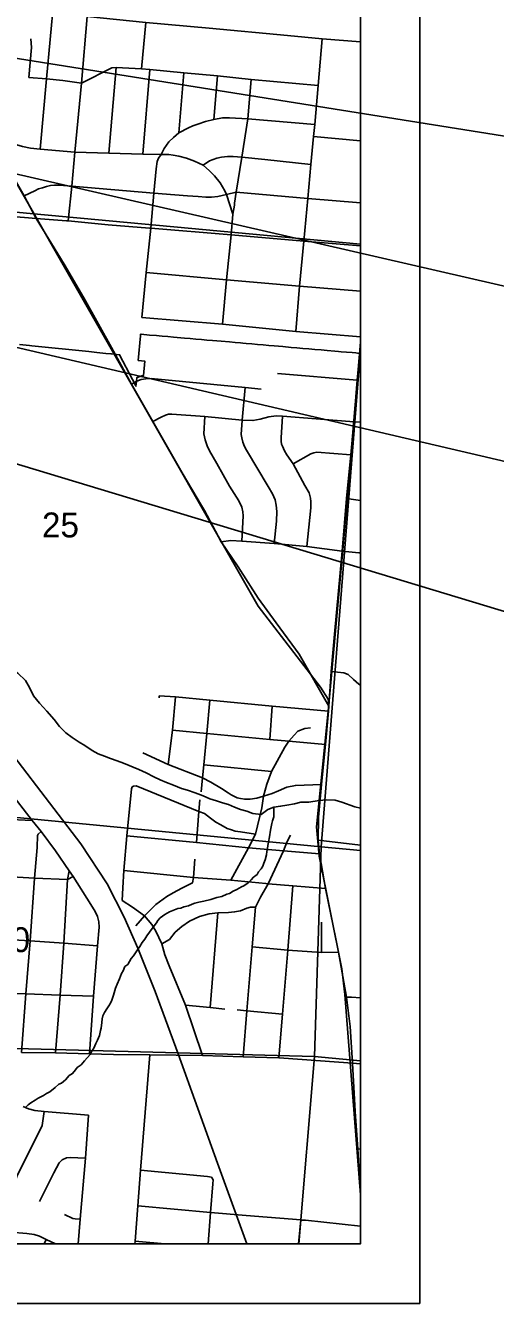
# Model space of a CAD drawing. Extents: x 0 to 34, y 0 to 22.
# Drawn here: x 8.337 to 9.127, y 14 to 16.149 of the extents above; entities that cross this region are included whole.
import ezdxf

# ---------------------------------------------------------------- set-up
doc = ezdxf.new("R2010")
doc.units = 0
for name, color, linetype in [('Default', 7, 'Continuous'), ('GM_X_City_Street', 7, 'Continuous'), ('GM_X_County_Road', 7, 'Continuous'), ('GM_X_Minor_River', 7, 'Continuous'), ('GM_X_Rail_Line', 7, 'Continuous'), ('GM_X_Section', 7, 'Continuous'), ('GM_X_Section_Text', 7, 'Continuous'), ('GM_X_State_Route', 7, 'Continuous'), ('GM_X_Township_Road', 7, 'Continuous'), ('SH_Data', 7, 'Continuous'), ('SH_Text', 7, 'Continuous')]:
    doc.layers.add(name, color=color, linetype=linetype)

msp = doc.modelspace()

# ---------------------------------------------------------------- linework, layer by layer
at = {"layer": 'Default'}
for points in [[(8.9, 15.7814), (8.9, 16.8048), (8.0016, 16.8868), (7.9035, 15.8736)], [(8.9, 15.6028), (8.9, 15.7814), (7.9035, 15.8736), (7.8278, 14.865), (8.8341, 14.7681)], [(8.9, 14.7619), (8.9, 15.6028), (8.8341, 14.7681)], [(8.9, 14.4077), (8.9, 14.7619), (8.8341, 14.7681), (8.8225, 14.415)], [(7.7734, 14.1), (8.7964, 14.1), (8.8225, 14.415), (7.7982, 14.4425)], [(8.7964, 14.1), (8.9, 14.1), (8.9, 14.4077), (8.8225, 14.415)]]:
    msp.add_lwpolyline(points, close=True, dxfattribs=at)
at = {"layer": 'GM_X_City_Street'}
for p, q in [((8.5321, 16.0763), (8.5389, 16.154)), ((8.4767, 15.9342), (8.4895, 16.0786)), ((8.5343, 15.9328), (8.5458, 16.0748)), ((8.6536, 15.991), (8.6598, 16.0643)), ((8.8213, 15.9624), (8.9, 15.9549)), ((8.3549, 15.8247), (8.4056, 15.8205)), ((8.7605, 15.5638), (8.8946, 15.5526)), ((8.8768, 15.3536), (8.9, 15.3501)), ((8.7474, 14.9484), (8.7515, 15.0045)), ((8.6369, 14.9057), (8.7502, 14.8945)), ((8.8291, 14.7791), (8.9, 14.7707)), ((8.6194, 14.7164), (8.6214, 14.7469)), ((8.6475, 14.4979), (8.6604, 14.6567)), ((8.8347, 14.59), (8.8343, 14.6409)), ((8.771, 14.4125), (8.8867, 14.4043)), ((8.8867, 14.4043), (8.9, 14.4032)), ((8.8954, 14.26), (8.9, 14.2595)), ((8.7961, 14.1), (8.7997, 14.1404)), ((8.3683, 14.1), (8.3717, 14.1074)), ((8.5713, 14.1), (8.521, 14.1049))]:
    msp.add_line(p, q, dxfattribs=at)
for points in [[(8.4086, 15.8203), (8.4148, 15.879), (8.42, 15.9362), (8.4311, 16.0521), (8.4407, 16.1639), (8.4425, 16.1849), (8.4481, 16.2479), (8.4567, 16.3286), (8.4603, 16.3382), (8.4723, 16.4504), (8.4774, 16.5183), (8.4829, 16.5851), (8.4866, 16.6299), (8.4884, 16.6515), (8.4965, 16.7464), (8.5006, 16.7499)], [(8.3616, 15.9413), (8.372, 16.0594), (8.3846, 16.1916)], [(8.4407, 16.1639), (8.5389, 16.154), (8.6455, 16.1443), (8.7774, 16.1321), (8.8358, 16.1268), (8.9, 16.1214)], [(8.3425, 16.0616), (8.3469, 16.1121), (8.3456, 16.1268)], [(8.7915, 15.6345), (8.7974, 15.7108), (8.8048, 15.7862), (8.8116, 15.8583), (8.8167, 15.9154), (8.8213, 15.9624), (8.8234, 15.9828), (8.8288, 16.0481), (8.8358, 16.1268)], [(8.3425, 16.0616), (8.372, 16.0594), (8.3996, 16.0567), (8.4311, 16.0521), (8.4822, 16.0777), (8.4895, 16.0786), (8.5321, 16.0763), (8.5458, 16.0748), (8.603, 16.0697), (8.6598, 16.0643), (8.7162, 16.0585), (8.8288, 16.0481)], [(8.5322, 15.6579), (8.5397, 15.7337), (8.5476, 15.8082), (8.5528, 15.8669), (8.5563, 15.9081), (8.5581, 15.9205), (8.5603, 15.9258), (8.5652, 15.9321), (8.57, 15.9422), (8.5777, 15.9533), (8.5857, 15.9609), (8.5945, 15.9686), (8.603, 16.0697)], [(8.688, 15.8471), (8.6884, 15.8502), (8.6913, 15.8688), (8.7005, 15.9274), (8.7106, 15.9922), (8.7162, 16.0585)], [(8.5945, 15.9686), (8.611, 15.9769), (8.6182, 15.9801), (8.6265, 15.9832), (8.6393, 15.9878), (8.6536, 15.991), (8.6678, 15.9936), (8.68, 15.9939), (8.7106, 15.9922), (8.8234, 15.9828)], [(8.2829, 15.9541), (8.2918, 15.9575), (8.2967, 15.9581), (8.3048, 15.9554), (8.3145, 15.9505), (8.3319, 15.9456), (8.3454, 15.9429), (8.3616, 15.9413), (8.42, 15.9362), (8.4767, 15.9342), (8.5343, 15.9328), (8.5652, 15.9321), (8.5778, 15.932), (8.5849, 15.931), (8.5949, 15.9292), (8.6077, 15.926), (8.6209, 15.921), (8.6355, 15.9139), (8.6461, 15.9046), (8.6547, 15.8961), (8.6639, 15.8847), (8.6721, 15.8708), (8.6746, 15.8651), (8.6856, 15.8318)], [(8.6355, 15.9139), (8.6464, 15.9216), (8.6586, 15.9262), (8.6666, 15.9278), (8.6766, 15.9289), (8.6858, 15.9285), (8.7005, 15.9274), (8.7393, 15.9236), (8.8167, 15.9154)], [(8.3344, 15.8628), (8.3525, 15.8712), (8.3589, 15.8741), (8.3652, 15.8761), (8.3722, 15.8784), (8.3788, 15.8799), (8.3858, 15.8804), (8.3933, 15.8807), (8.4148, 15.879), (8.5528, 15.8669), (8.588, 15.8642), (8.6092, 15.8625), (8.6273, 15.8613), (8.6401, 15.8604), (8.6497, 15.8606), (8.6604, 15.8617), (8.6746, 15.8651), (8.6913, 15.8688), (8.8116, 15.8583), (8.9, 15.8507)], [(8.6826, 15.7971), (8.6856, 15.8318), (8.688, 15.8471)], [(8.276, 15.8309), (8.3353, 15.8261), (8.3549, 15.8247)], [(8.4056, 15.8205), (8.4086, 15.8203), (8.4761, 15.8141), (8.5456, 15.8083)], [(8.5456, 15.8083), (8.5476, 15.8082), (8.6826, 15.7971), (8.8048, 15.7862), (8.9, 15.7783)], [(8.6682, 15.6468), (8.6749, 15.7215), (8.6826, 15.7971)], [(8.5397, 15.7337), (8.6749, 15.7215), (8.7974, 15.7108), (8.9, 15.7023)], [(8.5322, 15.6579), (8.6682, 15.6468), (8.7915, 15.6345), (8.9, 15.6253)], [(8.847, 15.0045), (8.8509, 15.0626), (8.8565, 15.1257), (8.8692, 15.2653), (8.8768, 15.3536), (8.8836, 15.427), (8.889, 15.4826), (8.8946, 15.5526), (8.9, 15.6118)], [(8.515, 15.5459), (8.5243, 15.5508), (8.5315, 15.5536), (8.5392, 15.555), (8.548, 15.5553), (8.7059, 15.54), (8.7333, 15.5377)], [(8.7552, 15.2782), (8.7587, 15.3153), (8.7595, 15.332), (8.7584, 15.3426), (8.7567, 15.3514), (8.7519, 15.3615), (8.7451, 15.374), (8.7083, 15.4351), (8.7049, 15.4413), (8.7021, 15.4482), (8.7003, 15.4554), (8.6997, 15.461), (8.7011, 15.4851), (8.7059, 15.54)], [(8.5509, 15.4831), (8.5649, 15.4905), (8.5721, 15.4938), (8.5775, 15.4952), (8.5827, 15.4957), (8.6381, 15.4917), (8.7011, 15.4851), (8.7191, 15.4846), (8.7316, 15.4868), (8.746, 15.491), (8.7582, 15.4926), (8.769, 15.492), (8.8821, 15.4831)], [(8.7008, 15.2821), (8.7026, 15.3243), (8.7024, 15.3314), (8.7003, 15.3389), (8.6953, 15.3496), (8.6801, 15.3743), (8.6587, 15.4123), (8.6464, 15.4339), (8.6424, 15.4423), (8.6388, 15.4521), (8.6369, 15.4622), (8.6381, 15.4917)], [(8.8096, 15.2727), (8.8165, 15.3379), (8.8166, 15.3482), (8.8161, 15.3541), (8.8139, 15.3629), (8.8067, 15.3755), (8.7866, 15.4119), (8.7763, 15.427), (8.7724, 15.4338), (8.7687, 15.4414), (8.7675, 15.4452), (8.7668, 15.4499), (8.7669, 15.4555), (8.769, 15.492)], [(8.8821, 15.4831), (8.889, 15.4826), (8.9, 15.4819)], [(8.7866, 15.4119), (8.8165, 15.4287), (8.8215, 15.4304), (8.8266, 15.4314), (8.8836, 15.427)], [(8.666, 15.2808), (8.6822, 15.2829), (8.7008, 15.2821), (8.7552, 15.2782), (8.8096, 15.2727), (8.8692, 15.2653), (8.8972, 15.2623), (8.9, 15.262)], [(8.4444, 14.4197), (8.451, 14.5166), (8.4579, 14.6015), (8.4606, 14.6326), (8.46, 14.6418), (8.4578, 14.6507), (8.4539, 14.659), (8.4466, 14.6709), (8.4168, 14.7182), (8.4105, 14.7274), (8.387, 14.761), (8.3629, 14.7939), (8.348, 14.8119), (8.268, 14.9151), (8.2279, 14.9702), (8.1705, 15.0446), (8.1397, 15.0843), (8.0736, 15.1714), (8.0394, 15.217), (8.0326, 15.2277), (8.0282, 15.2381)], [(8.8509, 15.0626), (8.872, 15.0602), (8.8792, 15.0574), (8.8885, 15.0494), (8.8972, 15.0413), (8.9, 15.0395)], [(8.5615, 15.0185), (8.5617, 15.0216), (8.5891, 15.0199), (8.647, 15.0147), (8.7515, 15.0045), (8.8464, 14.9958)], [(8.5769, 14.9064), (8.5839, 14.9638), (8.5891, 15.0199)], [(8.6322, 14.8606), (8.6344, 14.884), (8.6369, 14.9057), (8.6417, 14.9587), (8.647, 15.0147)], [(8.5839, 14.9638), (8.6417, 14.9587), (8.7474, 14.9484), (8.7796, 14.9453), (8.8413, 14.94)], [(8.6819, 14.7116), (8.7118, 14.7663), (8.7233, 14.7894), (8.7341, 14.8332), (8.737, 14.8533), (8.7427, 14.8733), (8.7502, 14.8945), (8.7729, 14.9357), (8.7796, 14.9453), (8.7887, 14.9559), (8.7947, 14.9624), (8.8066, 14.9671), (8.8161, 14.9679)], [(8.5341, 14.9259), (8.5769, 14.9064), (8.6344, 14.884), (8.6485, 14.8764), (8.6666, 14.8657), (8.6774, 14.8585), (8.6827, 14.8552), (8.688, 14.8524), (8.6928, 14.8505), (8.6986, 14.849), (8.7056, 14.8478), (8.7145, 14.8482), (8.7259, 14.8499), (8.737, 14.8533), (8.7513, 14.8576), (8.7621, 14.8621), (8.7763, 14.8682), (8.7908, 14.871), (8.8347, 14.8729)], [(7.8605, 14.8558), (7.8962, 14.8515), (7.9605, 14.8451), (8.0166, 14.8401), (8.0748, 14.8351), (8.1304, 14.8305), (8.1895, 14.8255), (8.2445, 14.8198), (8.3016, 14.8145), (8.348, 14.8119)], [(8.4995, 14.6775), (8.5007, 14.6987), (8.5023, 14.7281), (8.5072, 14.7862), (8.515, 14.8654), (8.516, 14.8686), (8.5185, 14.87)], [(8.5185, 14.87), (8.5228, 14.8704), (8.6282, 14.8275), (8.6378, 14.8241), (8.6478, 14.8162), (8.6571, 14.8096), (8.6653, 14.8046), (8.676, 14.7989), (8.683, 14.7962), (8.6891, 14.7943), (8.6984, 14.7928), (8.7233, 14.7894)], [(8.6246, 14.775), (8.6282, 14.8275), (8.63, 14.847)], [(8.3303, 14.4222), (8.3373, 14.5206), (8.3446, 14.6097), (8.352, 14.715), (8.3563, 14.767), (8.3572, 14.7868), (8.3584, 14.7891), (8.3629, 14.7939)], [(8.5072, 14.7862), (8.6246, 14.775), (8.7118, 14.7663), (8.7708, 14.7614), (8.831, 14.7559)], [(8.566, 14.6046), (8.5787, 14.6119), (8.5887, 14.6242), (8.5995, 14.634), (8.6127, 14.6426), (8.6293, 14.6506), (8.6455, 14.6549), (8.6604, 14.6567), (8.6784, 14.6576), (8.6884, 14.6585), (8.6983, 14.6604), (8.7092, 14.6648), (8.7153, 14.6665), (8.7236, 14.6665), (8.7317, 14.6833), (8.7448, 14.7059), (8.7708, 14.7614), (8.7763, 14.7759), (8.7825, 14.7876)], [(7.8513, 14.7388), (7.8873, 14.7373), (7.953, 14.735), (8.0084, 14.7327), (8.0654, 14.7306), (8.1228, 14.7282), (8.1823, 14.7266), (8.238, 14.7228), (8.2946, 14.7187), (8.352, 14.715), (8.4076, 14.713), (8.4168, 14.7182)], [(8.3873, 14.4212), (8.3951, 14.5182), (8.4012, 14.6061), (8.4076, 14.713), (8.4105, 14.7274)], [(8.5023, 14.7281), (8.6194, 14.7164), (8.6819, 14.7116), (8.7409, 14.7063)], [(8.5224, 14.635), (8.5368, 14.6519), (8.5557, 14.6711), (8.5744, 14.6844), (8.585, 14.6906), (8.5998, 14.6986), (8.6174, 14.7072), (8.6194, 14.7164)], [(8.7409, 14.7063), (8.7448, 14.7059), (8.7863, 14.7022), (8.841, 14.698)], [(8.7627, 14.4131), (8.7691, 14.4865), (8.7779, 14.594), (8.7863, 14.7022)], [(8.6343, 14.4169), (8.6057, 14.5014), (8.5784, 14.5679), (8.5712, 14.5863), (8.566, 14.6046), (8.5561, 14.6259), (8.549, 14.637), (8.5368, 14.6519), (8.5165, 14.6662), (8.4995, 14.6775)], [(8.703, 14.4147), (8.7092, 14.4921), (8.718, 14.5999), (8.7236, 14.6665)], [(8.1762, 14.6207), (8.2309, 14.6169), (8.2875, 14.6133), (8.3446, 14.6097), (8.4012, 14.6061), (8.4579, 14.6015)], [(8.718, 14.5999), (8.7779, 14.594), (8.8347, 14.59), (8.8632, 14.5908)], [(7.8356, 14.5383), (7.871, 14.5362), (7.9457, 14.5339), (8.0225, 14.5306), (8.0994, 14.5281), (8.1663, 14.526), (8.2236, 14.5242), (8.2789, 14.5224), (8.3373, 14.5206), (8.3951, 14.5182), (8.451, 14.5166)], [(8.8767, 14.5148), (8.8851, 14.5151), (8.9, 14.5137)], [(8.6057, 14.5014), (8.6475, 14.4979), (8.6721, 14.495)], [(8.6929, 14.4936), (8.7092, 14.4921), (8.7691, 14.4865)], [(8.3303, 14.4222), (8.3873, 14.4212), (8.4444, 14.4197), (8.485, 14.4189), (8.5461, 14.4181), (8.6343, 14.4169), (8.703, 14.4147), (8.7627, 14.4131), (8.771, 14.4125)], [(8.5206, 14.1), (8.521, 14.1049), (8.5259, 14.1639), (8.5302, 14.2242), (8.5461, 14.4181)], [(8.3099, 14.1), (8.3117, 14.1199), (8.3174, 14.1858), (8.3181, 14.1972), (8.3194, 14.205), (8.3222, 14.2135), (8.3646, 14.2994), (8.3681, 14.3228)], [(8.3329, 14.3311), (8.342, 14.327), (8.3528, 14.3243), (8.3681, 14.3228), (8.4428, 14.3167)], [(8.4253, 14.1), (8.4286, 14.1416), (8.4375, 14.2441), (8.4428, 14.3167)], [(8.3603, 14.1717), (8.3846, 14.2194), (8.3935, 14.2362), (8.3985, 14.2413), (8.4055, 14.2446), (8.4122, 14.2456), (8.4375, 14.2441)], [(8.5302, 14.2242), (8.6429, 14.2132), (8.6494, 14.2124)], [(8.6438, 14.1), (8.6478, 14.1531), (8.6519, 14.2014), (8.6523, 14.2081), (8.6494, 14.2124)], [(8.5259, 14.1639), (8.6478, 14.1531), (8.708, 14.1481), (8.7997, 14.1404), (8.8015, 14.1403), (8.8075, 14.1398), (8.9, 14.1299)], [(8.4025, 14.1496), (8.4164, 14.1431), (8.4201, 14.1423), (8.4286, 14.1416)], [(8.3117, 14.1199), (8.3388, 14.1177), (8.3516, 14.1159), (8.3606, 14.1132), (8.3717, 14.1074), (8.3871, 14.1)]]:
    msp.add_lwpolyline(points, dxfattribs=at)
at = {"layer": 'GM_X_County_Road'}
for points in [[(8.3549, 15.8247), (8.3344, 15.8628), (8.3116, 15.9031), (8.2833, 15.9532)], [(8.4849, 15.6015), (8.4845, 15.6023), (8.4349, 15.6911), (8.4016, 15.7479), (8.3549, 15.8247)], [(8.6376, 15.3333), (8.6329, 15.3421), (8.6002, 15.3967), (8.5509, 15.4831), (8.515, 15.5459), (8.4849, 15.6015)], [(8.847, 15.0045), (8.7972, 15.0916), (8.7583, 15.1443), (8.7278, 15.1859), (8.6945, 15.2386), (8.666, 15.2808), (8.6376, 15.3333)], [(8.8867, 14.4043), (8.8825, 14.4659), (8.8767, 14.5148), (8.8632, 14.5908), (8.8586, 14.613), (8.841, 14.698), (8.831, 14.7559), (8.8291, 14.7791), (8.8296, 14.8179), (8.8347, 14.8729), (8.8413, 14.94), (8.8464, 14.9958), (8.847, 15.0045)], [(8.9, 14.1901), (8.8974, 14.2305), (8.8954, 14.26), (8.8913, 14.3229), (8.8867, 14.4043)]]:
    msp.add_lwpolyline(points, dxfattribs=at)
at = {"layer": 'GM_X_Minor_River'}
for points in [[(8.4797, 14.9164), (8.4699, 14.9202), (8.4591, 14.9244), (8.449, 14.9297), (8.4368, 14.9381), (8.4268, 14.9438), (8.4153, 14.9518), (8.4049, 14.9594), (8.3939, 14.9701), (8.3849, 14.9822), (8.3725, 14.9959), (8.3604, 15.0097), (8.3502, 15.0218), (8.3435, 15.0357), (8.3367, 15.0478), (8.3239, 15.06), (8.3124, 15.0673), (8.3008, 15.073), (8.2885, 15.0784), (8.2821, 15.0805)], [(8.9, 14.8327), (8.8904, 14.8351), (8.8687, 14.8427), (8.8574, 14.8461), (8.8431, 14.847), (8.8305, 14.8456), (8.8133, 14.8432), (8.8, 14.8429), (8.7893, 14.8399), (8.7763, 14.8381), (8.7656, 14.8362), (8.7542, 14.8347), (8.7445, 14.8305), (8.7332, 14.8225), (8.7192, 14.8238), (8.7088, 14.8276), (8.6982, 14.8306), (8.6885, 14.8348), (8.678, 14.839), (8.6679, 14.8416), (8.6581, 14.845), (8.6465, 14.8488), (8.6353, 14.8538), (8.6222, 14.8588), (8.6091, 14.8631), (8.5989, 14.8661), (8.5855, 14.8716), (8.5739, 14.8762), (8.5634, 14.8803), (8.5526, 14.8853), (8.5399, 14.8922), (8.5272, 14.898), (8.5014, 14.9088), (8.4909, 14.9126), (8.4797, 14.9164)], [(8.7542, 14.8347), (8.7541, 14.8185), (8.7524, 14.8113), (8.7511, 14.8072), (8.7499, 14.8015), (8.749, 14.7958), (8.7472, 14.7848), (8.7454, 14.7757), (8.7445, 14.7701), (8.7436, 14.7651), (8.7424, 14.7599), (8.7419, 14.7545), (8.7397, 14.7462), (8.7377, 14.7406), (8.7357, 14.7353), (8.7333, 14.7308), (8.7286, 14.726), (8.7262, 14.7215), (8.7204, 14.7167), (8.7161, 14.7122), (8.711, 14.7074), (8.7041, 14.7023), (8.6998, 14.7005), (8.6921, 14.6961), (8.686, 14.6932), (8.6798, 14.6895), (8.6756, 14.6881), (8.6671, 14.6845), (8.6587, 14.6825), (8.6483, 14.6793), (8.6365, 14.6762), (8.6285, 14.6748), (8.6216, 14.6731), (8.6173, 14.6713), (8.6108, 14.6684), (8.6028, 14.6671), (8.5978, 14.6646), (8.5932, 14.6639), (8.5871, 14.6618), (8.579, 14.6586), (8.5709, 14.6542), (8.5635, 14.6487), (8.5593, 14.6442), (8.5569, 14.6401), (8.5514, 14.633), (8.5455, 14.6244), (8.5407, 14.6181), (8.5372, 14.6128), (8.5332, 14.6069), (8.5289, 14.6005), (8.5261, 14.5964), (8.523, 14.5911), (8.5186, 14.5848), (8.5143, 14.5799), (8.5088, 14.5702), (8.5037, 14.5665), (8.5009, 14.5594), (8.4981, 14.5549), (8.4948, 14.5458), (8.4908, 14.5368), (8.4884, 14.5304), (8.485, 14.5183), (8.4818, 14.51), (8.4798, 14.5047), (8.477, 14.5006), (8.4734, 14.4954), (8.4695, 14.4894), (8.4671, 14.4834), (8.4658, 14.4785), (8.4649, 14.4724), (8.4639, 14.4629), (8.4627, 14.4588), (8.4613, 14.4508), (8.4581, 14.4429), (8.4553, 14.4369), (8.4517, 14.429), (8.4477, 14.4234), (8.4453, 14.4185), (8.4359, 14.4077), (8.4304, 14.401), (8.4239, 14.397), (8.4207, 14.3929), (8.416, 14.3865), (8.4102, 14.3833), (8.4039, 14.3758), (8.3974, 14.3706), (8.3931, 14.3685), (8.3869, 14.3629), (8.378, 14.3559), (8.3722, 14.353), (8.3672, 14.3497), (8.3583, 14.3454), (8.3533, 14.3417), (8.3456, 14.3373), (8.3413, 14.334), (8.3374, 14.3299)]]:
    msp.add_lwpolyline(points, dxfattribs=at)
at = {"layer": 'GM_X_Rail_Line'}
for points in [[(7.8169, 16.8999), (7.8105, 16.8874), (7.814, 16.6995), (7.8204, 16.6764), (7.8335, 16.6519), (8.0389, 16.3719), (8.2579, 15.9951), (8.7281, 15.1727), (8.8328, 15.0366), (8.8456, 15.016), (8.8469, 15.007)], [(8.9, 15.6165), (8.8706, 15.2674), (8.8469, 15.007)], [(8.8469, 15.007), (8.826, 14.8017), (8.8304, 14.7521), (8.8688, 14.5625), (8.8737, 14.5195), (8.9, 14.1824)], [(8.2642, 14.989), (8.4296, 14.773), (8.4739, 14.7055), (8.5029, 14.6498), (8.5255, 14.5972), (8.555, 14.5248), (8.5935, 14.4199), (8.6598, 14.2358), (8.709, 14.1)]]:
    msp.add_lwpolyline(points, dxfattribs=at)
at = {"layer": 'GM_X_Section'}
msp.add_lwpolyline([(7.8278, 14.865), (8.8341, 14.7681), (8.8225, 14.415), (7.7982, 14.4425)], close=True, dxfattribs=at)
at = {"layer": 'GM_X_State_Route'}
msp.add_lwpolyline([(8.3266, 15.6126), (8.3434, 15.6109), (8.3472, 15.6105), (8.4434, 15.6006), (8.4568, 15.5993), (8.4719, 15.5977), (8.4804, 15.5969), (8.4814, 15.5968), (8.4878, 15.5961), (8.4896, 15.5959), (8.4951, 15.5954), (8.4951, 15.5953), (8.5167, 15.5536), (8.5194, 15.5485), (8.5224, 15.5426), (8.5225, 15.5425), (8.5225, 15.5426), (8.5232, 15.5503), (8.5238, 15.5569), (8.5239, 15.557), (8.5247, 15.5573), (8.5255, 15.5576), (8.5263, 15.5579), (8.5272, 15.5582), (8.528, 15.5585), (8.5289, 15.5588), (8.5297, 15.559), (8.5306, 15.5593), (8.5315, 15.5595), (8.5323, 15.5597), (8.5332, 15.5599), (8.5341, 15.5601), (8.535, 15.5602), (8.5352, 15.5603), (8.5373, 15.5847), (8.5264, 15.5857), (8.5302, 15.627), (8.5304, 15.6298), (8.5313, 15.6298), (8.5455, 15.6285), (8.5571, 15.6275), (8.5618, 15.6271), (8.5665, 15.6267), (8.576, 15.6259), (8.5854, 15.625), (8.6043, 15.6234), (8.6137, 15.6226), (8.6232, 15.6218), (8.6326, 15.6209), (8.642, 15.6201), (8.6515, 15.6193), (8.6656, 15.6181), (8.6798, 15.6168), (8.6892, 15.616), (8.6986, 15.6152), (8.7021, 15.6149), (8.7081, 15.6144), (8.7175, 15.6136), (8.7269, 15.6127), (8.7364, 15.6119), (8.7458, 15.6111), (8.7552, 15.6103), (8.7694, 15.609), (8.7835, 15.6078), (8.793, 15.607), (8.8032, 15.6061), (8.8133, 15.6052), (8.8235, 15.6043), (8.8337, 15.6034), (8.8439, 15.6025), (8.857, 15.6014), (8.863, 15.6009), (8.8674, 15.6005), (8.8768, 15.5997), (8.8862, 15.5989), (8.8924, 15.5983), (8.8949, 15.5981), (8.8992, 15.5977), (8.8995, 15.5977), (8.9, 15.5977), (8.9, 20.2522)], dxfattribs=at)
at = {"layer": 'GM_X_Township_Road'}
msp.add_lwpolyline([(3.9251, 14.1), (8.9, 14.1), (8.9, 20.9)], dxfattribs=at)
at = {"layer": 'SH_Data'}
for p, q in [((9, 21), (9, 14)), ((8.9, 20.9), (8.9, 14.1)), ((2.1, 14.1), (8.9, 14.1)), ((2, 14), (9, 14))]:
    msp.add_line(p, q, dxfattribs=at)
at = {"layer": 'SH_Text'}
for points in [[(5.5598, 16.5345), (9.346, 15.9306), (10.7296, 15.939), (10.7249, 15.654), (9.3684, 15.6583)], [(5.4805, 16.2716), (9.333, 15.3718), (10.6987, 15.3733), (10.6963, 15.0992), (9.3554, 15.0994)]]:
    msp.add_lwpolyline(points, close=True, dxfattribs=at)

# ---------------------------------------------------------------- texts
at = {"layer": 'GM_X_Section_Text'}
for s, p in [('25', (8.3645, 15.2882)), ('30', (8.2824, 14.5908))]:
    msp.add_text(s, height=0.04186, rotation=0, dxfattribs=at).set_placement(p)

doc.saveas('drawing.dxf')
